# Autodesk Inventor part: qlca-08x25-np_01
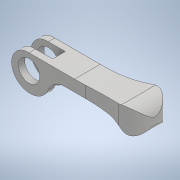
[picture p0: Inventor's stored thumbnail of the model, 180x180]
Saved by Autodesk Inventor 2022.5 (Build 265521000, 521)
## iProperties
Part Number: qlca-08x25-np_01
Material: 一般
Document SubType Name: Modeling
Designer: ImaoCorp
Density: 1 g/cm^3
Appearance: 既定
Author: ImaoCorp
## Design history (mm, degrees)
feature "qlca-08x25-np_01"
node "ソリッド1"
